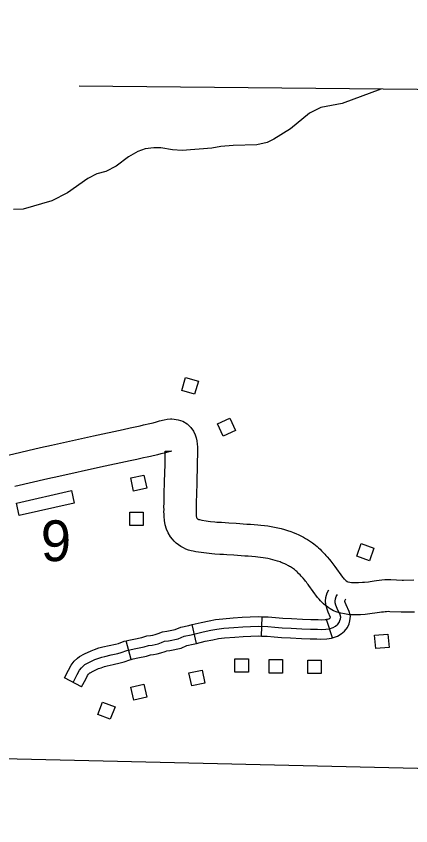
# Model space of a CAD drawing. Extents: x -19 to 366, y -4 to 359.
# Drawn here: x 137.637 to 138.218, y 202.996 to 204.187 of the extents above; entities that cross this region are included whole.
import ezdxf

# ---------------------------------------------------------------- set-up
doc = ezdxf.new("R2010")
doc.units = 0
for name, color, linetype in [('Level 10', 7, 'Continuous'), ('Level 2', 7, 'Continuous'), ('Level 32', 7, 'Continuous'), ('Level 35', 7, 'Continuous'), ('Level 5', 7, 'Continuous'), ('Level 56', 7, 'Continuous'), ('Level 60', 7, 'Continuous')]:
    doc.layers.add(name, color=color, linetype=linetype)

msp = doc.modelspace()

# ---------------------------------------------------------------- linework, layer by layer
at = {"layer": 'Level 10'}
for p, q in [((137.6726, 203.552), (137.6889, 203.5558)), ((137.6247, 203.5411), (137.6726, 203.552)), ((137.865, 203.5468), (137.8653, 203.5468)), ((137.6832, 203.5059), (137.6349, 203.4949)), ((137.6994, 203.5096), (137.6832, 203.5059)), ((137.6832, 203.5059), (137.6832, 203.5059)), ((137.6993, 203.5096), (137.6994, 203.5096)), ((138.1236, 203.355), (138.1228, 203.3556)), ((138.096, 203.3166), (138.0952, 203.3172))]:
    msp.add_line(p, q, dxfattribs=at)
for points in [[(137.6889, 203.5558), (137.7504, 203.5695), (137.7943, 203.5789), (137.8043, 203.5811), (137.8142, 203.5831), (137.819, 203.5842), (137.8239, 203.5853), (137.8333, 203.5875), (137.8382, 203.5887), (137.8431, 203.5899), (137.8478, 203.5912), (137.8543, 203.5929), (137.8589, 203.5938), (137.8638, 203.5942), (137.8659, 203.5942)], [(137.8659, 203.5942), (137.8691, 203.5941), (137.8753, 203.5931), (137.882, 203.5908), (137.8885, 203.5868), (137.8937, 203.5817), (137.8977, 203.5761), (137.9001, 203.5706), (137.9016, 203.5662), (137.9026, 203.5618), (137.9032, 203.5573), (137.9035, 203.5532), (137.9035, 203.5473), (137.9032, 203.5261), (137.9024, 203.5011), (137.902, 203.4823), (137.9019, 203.4789), (137.9018, 203.476), (137.9017, 203.473), (137.9016, 203.47), (137.9016, 203.4642), (137.9016, 203.461), (137.9016, 203.4581), (137.9017, 203.4552), (137.9017, 203.4526), (137.9018, 203.451), (137.902, 203.4502), (137.9023, 203.4492), (137.9027, 203.4482), (137.9032, 203.4475), (137.9035, 203.4471), (137.9035, 203.4471), (137.9037, 203.447), (137.9042, 203.4467), (137.9043, 203.4466), (137.9047, 203.4465), (137.9051, 203.4463), (137.9065, 203.4461), (137.9097, 203.4454), (137.9162, 203.4444), (137.9193, 203.4439), (137.9225, 203.4435), (137.929, 203.4428), (137.932, 203.4425), (137.9391, 203.4421), (137.9444, 203.4418), (137.9496, 203.4415), (137.9605, 203.4408), (137.9658, 203.4404), (137.971, 203.44), (137.9764, 203.4396), (137.9816, 203.4393), (137.9923, 203.4385), (137.997, 203.4381), (138.0021, 203.4375), (138.0069, 203.4369), (138.0119, 203.4361), (138.0168, 203.4351), (138.0217, 203.434), (138.0265, 203.4328), (138.0314, 203.4315), (138.0362, 203.4299), (138.0407, 203.4284), (138.0436, 203.4274), (138.0491, 203.4251), (138.0517, 203.424), (138.0546, 203.4227), (138.0598, 203.42), (138.0626, 203.4185), (138.0654, 203.4167), (138.0701, 203.4137), (138.0726, 203.4119), (138.0748, 203.4103), (138.0772, 203.4085), (138.0795, 203.4065), (138.0818, 203.4045), (138.0839, 203.4025), (138.0861, 203.4003), (138.088, 203.3982), (138.0895, 203.3965), (138.0909, 203.395), (138.0926, 203.3931), (138.0944, 203.3912), (138.0978, 203.3872), (138.0996, 203.385), (138.1013, 203.3829), (138.1028, 203.3809), (138.1043, 203.3789), (138.1058, 203.3769), (138.1171, 203.3612), (138.1178, 203.3604), (138.119, 203.3591), (138.1198, 203.3583), (138.1212, 203.3571), (138.1224, 203.3559), (138.1236, 203.355)], [(137.8653, 203.5468), (137.8651, 203.5468), (137.8649, 203.5468), (137.86, 203.5454), (137.8547, 203.544), (137.8498, 203.5428), (137.8447, 203.5415), (137.8344, 203.5391), (137.8293, 203.538), (137.8241, 203.5368), (137.8141, 203.5347), (137.8043, 203.5326), (137.7606, 203.5232), (137.6993, 203.5096)], [(138.0952, 203.3172), (138.0919, 203.3196), (138.0891, 203.3223), (138.0869, 203.3242), (138.0845, 203.3267), (138.0825, 203.3289), (138.0801, 203.3317), (138.0676, 203.3489), (138.0664, 203.3506), (138.0651, 203.3523), (138.0639, 203.3539), (138.0626, 203.3555), (138.0616, 203.3568), (138.059, 203.3597), (138.0576, 203.3613), (138.0562, 203.3628), (138.0545, 203.3646), (138.0529, 203.3664), (138.0519, 203.3675), (138.0508, 203.3687), (138.0497, 203.3697), (138.0485, 203.3707), (138.0475, 203.3716), (138.0462, 203.3725), (138.0448, 203.3736), (138.0436, 203.3745), (138.0404, 203.3765), (138.0391, 203.3773), (138.0375, 203.3782), (138.034, 203.38), (138.0323, 203.3808), (138.0304, 203.3816), (138.0267, 203.3831), (138.0251, 203.3837), (138.0214, 203.385), (138.0179, 203.3861), (138.0144, 203.387), (138.0108, 203.388), (138.0072, 203.3888), (138.0036, 203.3895), (138, 203.39), (137.9963, 203.3905), (137.9926, 203.391), (137.9887, 203.3912), (137.9782, 203.3921), (137.973, 203.3924), (137.9677, 203.3928), (137.9624, 203.3932), (137.9571, 203.3936), (137.9468, 203.3942), (137.9416, 203.3945), (137.9362, 203.3949), (137.9289, 203.3953), (137.9246, 203.3956), (137.9169, 203.3965), (137.9128, 203.397), (137.9088, 203.3976), (137.9011, 203.3989), (137.8971, 203.3997), (137.8942, 203.4002), (137.8904, 203.4013), (137.8866, 203.4027), (137.8828, 203.4044), (137.8789, 203.4065), (137.8757, 203.4088), (137.8724, 203.4113), (137.8693, 203.4144), (137.8667, 203.4172), (137.864, 203.4207), (137.8606, 203.4264), (137.8581, 203.4322), (137.856, 203.4383), (137.8548, 203.4447), (137.8544, 203.4505), (137.8543, 203.4543), (137.8542, 203.4576), (137.8543, 203.461), (137.8542, 203.4642), (137.8543, 203.4709), (137.8544, 203.4741), (137.8544, 203.4774), (137.8546, 203.4807), (137.8547, 203.4835), (137.8551, 203.5023), (137.8558, 203.5272), (137.8561, 203.547), (137.865, 203.5468)], [(138.1228, 203.3556), (138.1234, 203.3552), (138.124, 203.3549), (138.1246, 203.3546), (138.1254, 203.3544), (138.1276, 203.354), (138.1301, 203.3536), (138.1327, 203.3534), (138.1355, 203.3533), (138.1382, 203.3533), (138.1406, 203.3534), (138.1465, 203.3538), (138.1492, 203.3541), (138.1552, 203.3547), (138.1579, 203.3551), (138.1638, 203.356), (138.167, 203.3565), (138.1709, 203.3571), (138.175, 203.3576), (138.1795, 203.3579), (138.1837, 203.358), (138.1879, 203.358), (138.205, 203.3572), (138.207, 203.3572), (138.2222, 203.3573)], [(138.223, 203.3099), (138.2067, 203.3098), (138.2035, 203.3099), (138.1867, 203.3106), (138.1842, 203.3107), (138.1818, 203.3106), (138.1796, 203.3104), (138.1772, 203.3101), (138.1744, 203.3097), (138.1713, 203.3092), (138.1645, 203.3082), (138.1608, 203.3077), (138.1539, 203.307), (138.1503, 203.3066), (138.1434, 203.3062), (138.1393, 203.306), (138.1345, 203.306), (138.1298, 203.3061), (138.1248, 203.3066), (138.1198, 203.3073), (138.1147, 203.3083), (138.1092, 203.3097), (138.1038, 203.312), (138.0988, 203.3146), (138.096, 203.3166)]]:
    msp.add_lwpolyline(points, dxfattribs=at)
at = {"layer": 'Level 2'}
msp.add_lwpolyline([(139.3896, 204.0685), (138.383, 204.0778), (138.3761, 204.0776), (137.7294, 204.084)], dxfattribs=at)
at = {"layer": 'Level 32'}
for p, q in [((137.9976, 203.2748), (137.9985, 203.3032)), ((137.9022, 203.264), (137.8957, 203.2916)), ((138.1024, 203.2721), (138.0932, 203.2989)), ((137.8058, 203.2403), (137.7986, 203.2678)), ((137.733, 203.1998), (137.7079, 203.2132))]:
    msp.add_line(p, q, dxfattribs=at)
for points in [[(138.0932, 203.2989), (138.0971, 203.3003), (138.0984, 203.3011), (138.0995, 203.302), (138.0959, 203.3098), (138.0937, 203.3159), (138.0923, 203.3217), (138.0921, 203.3263), (138.0924, 203.3317), (138.0944, 203.3383), (138.0969, 203.3429)], [(137.7204, 203.2065), (137.7266, 203.218), (137.7297, 203.2244), (137.7326, 203.2282), (137.7361, 203.2315), (137.7377, 203.2328), (137.7434, 203.2357), (137.7523, 203.24), (137.7568, 203.2415), (137.7626, 203.2438), (137.7672, 203.2448), (137.7765, 203.2469), (137.7862, 203.2491), (137.7913, 203.2504), (137.7997, 203.2534), (137.8058, 203.255), (137.8128, 203.2565), (137.825, 203.259), (137.8315, 203.261), (137.8366, 203.2615), (137.8411, 203.2624), (137.8455, 203.2635), (137.8508, 203.2654), (137.8552, 203.2672), (137.8607, 203.2677), (137.8751, 203.2706), (137.8837, 203.2744), (137.8941, 203.2767), (137.912, 203.2809), (137.9234, 203.2832), (137.9322, 203.2849), (137.9421, 203.2861), (137.9571, 203.2873), (137.9701, 203.2884), (137.9818, 203.2889), (137.9928, 203.2891), (138.0071, 203.2887), (138.0173, 203.2879), (138.028, 203.287), (138.0413, 203.2863), (138.0573, 203.2855), (138.0698, 203.285), (138.0802, 203.2848), (138.0854, 203.2844), (138.0926, 203.2848), (138.0977, 203.2854), (138.1033, 203.2874), (138.1067, 203.2895), (138.1099, 203.2921), (138.1121, 203.2949), (138.1132, 203.2974), (138.114, 203.3), (138.1143, 203.3027), (138.1134, 203.3058), (138.1091, 203.3153), (138.1073, 203.32), (138.1064, 203.3237), (138.1063, 203.3261), (138.1065, 203.3293), (138.1076, 203.3328), (138.1094, 203.3361)], [(138.1024, 203.2721), (138.1095, 203.2745), (138.1151, 203.278), (138.12, 203.2821), (138.1242, 203.2873), (138.1266, 203.2925), (138.1279, 203.2971), (138.1288, 203.3038), (138.1268, 203.3108), (138.1222, 203.3207), (138.1209, 203.3242), (138.1206, 203.3256), (138.1206, 203.326), (138.1206, 203.3268), (138.1208, 203.3273), (138.1219, 203.3293)], [(137.8957, 203.2916), (137.9089, 203.2947), (137.9206, 203.2971), (137.93, 203.299), (137.9407, 203.3002), (137.956, 203.3014), (137.9691, 203.3026), (137.9813, 203.3031), (137.9928, 203.3034), (137.9985, 203.3032)], [(137.9985, 203.3032), (138.0078, 203.3029), (138.0185, 203.3021), (138.029, 203.3012), (138.0421, 203.3005), (138.0579, 203.2997), (138.0702, 203.2992), (138.081, 203.299), (138.0857, 203.2986), (138.0913, 203.2989), (138.0944, 203.2993), (138.0932, 203.2989)], [(137.7986, 203.2678), (137.8025, 203.2688), (137.8099, 203.2704), (137.8215, 203.2728), (137.8288, 203.2749), (137.8344, 203.2755), (137.8379, 203.2762), (137.8413, 203.2771), (137.8457, 203.2787), (137.8519, 203.2811), (137.8586, 203.2818), (137.8708, 203.2843), (137.8792, 203.288), (137.8909, 203.2905), (137.8957, 203.2916)], [(137.7079, 203.2132), (137.7139, 203.2244), (137.7175, 203.2319), (137.722, 203.2378), (137.7268, 203.2422), (137.73, 203.2448), (137.7371, 203.2484), (137.7469, 203.2531), (137.7519, 203.2549), (137.7584, 203.2574), (137.7641, 203.2587), (137.7734, 203.2608), (137.7829, 203.2629), (137.7871, 203.264), (137.7955, 203.267), (137.7986, 203.2678)], [(137.9022, 203.264), (137.915, 203.267), (137.9262, 203.2692), (137.9344, 203.2709), (137.9435, 203.272), (137.9583, 203.2731), (137.971, 203.2742), (137.9823, 203.2747), (137.9927, 203.2749), (137.9976, 203.2748)], [(137.9976, 203.2748), (138.0063, 203.2745), (138.0162, 203.2738), (138.0271, 203.2728), (138.0406, 203.2721), (138.0566, 203.2713), (138.0694, 203.2708), (138.0794, 203.2706), (138.0852, 203.2701), (138.094, 203.2706), (138.101, 203.2716), (138.1025, 203.2721)], [(137.8058, 203.2403), (137.809, 203.2412), (137.8157, 203.2426), (137.8285, 203.2452), (137.8343, 203.247), (137.8388, 203.2474), (137.8443, 203.2485), (137.8497, 203.2499), (137.8558, 203.2522), (137.8586, 203.2532), (137.8628, 203.2536), (137.8795, 203.257), (137.8881, 203.2608), (137.8972, 203.2628), (137.9022, 203.264)], [(137.733, 203.1998), (137.7393, 203.2115), (137.7419, 203.2169), (137.7432, 203.2186), (137.7453, 203.2207), (137.7455, 203.2208), (137.7498, 203.223), (137.7577, 203.2268), (137.7617, 203.2282), (137.7668, 203.2301), (137.7704, 203.231), (137.7795, 203.233), (137.7895, 203.2353), (137.7955, 203.2368), (137.8039, 203.2398), (137.8058, 203.2403)]]:
    msp.add_lwpolyline(points, dxfattribs=at)
at = {"layer": 'Level 35'}
msp.add_lwpolyline([(138.1735, 204.0796), (138.1166, 204.0584), (138.0852, 204.0523), (138.0686, 204.0439), (138.0406, 204.0212), (138.0161, 204.006), (138.0059, 204.0011), (137.9907, 203.9976), (137.956, 203.9965), (137.9378, 203.995), (137.9246, 203.9927), (137.8811, 203.9893), (137.8668, 203.99), (137.8494, 203.993), (137.8392, 203.993), (137.8263, 203.9915), (137.8157, 203.9877), (137.8018, 203.9801), (137.784, 203.9661), (137.7685, 203.9581), (137.7553, 203.9547), (137.7421, 203.9479), (137.7122, 203.927), (137.6892, 203.9152), (137.6468, 203.9027), (137.6325, 203.9023)], dxfattribs=at)
at = {"layer": 'Level 5'}
msp.add_lwpolyline([(137.3855, 203.0998), (138.3744, 203.0767)], dxfattribs=at)
at = {"layer": 'Level 56'}
for points in [[(137.8993, 203.6308), (137.8804, 203.6362), (137.8858, 203.6552), (137.9048, 203.6498)], [(137.9413, 203.5689), (137.9331, 203.5868), (137.951, 203.5951), (137.9593, 203.5772)], [(137.8095, 203.4881), (137.8052, 203.5073), (137.8246, 203.5116), (137.8288, 203.4923)], [(137.6413, 203.452), (137.6371, 203.4704), (137.7179, 203.4887), (137.7221, 203.4702)], [(137.8041, 203.4375), (137.804, 203.4572), (137.8238, 203.4572), (137.8238, 203.4375)], [(138.1632, 203.4041), (138.1565, 203.3856), (138.1379, 203.3922), (138.1445, 203.4108)], [(138.1658, 203.2562), (138.1641, 203.2758), (138.1837, 203.2776), (138.1855, 203.2579)], [(137.9587, 203.2214), (137.9586, 203.2411), (137.9784, 203.2411), (137.9784, 203.2214)], [(138.0091, 203.2203), (138.0091, 203.24), (138.0289, 203.24), (138.0289, 203.2203)], [(138.066, 203.2198), (138.0659, 203.2395), (138.0857, 203.2395), (138.0857, 203.2198)], [(137.8951, 203.2013), (137.891, 203.2205), (137.9103, 203.2247), (137.9145, 203.2054)], [(137.829, 203.1848), (137.8097, 203.1804), (137.8054, 203.1997), (137.8246, 203.2041)], [(137.7568, 203.1593), (137.7639, 203.1777), (137.7823, 203.1706), (137.7752, 203.1522)]]:
    msp.add_lwpolyline(points, close=True, dxfattribs=at)
at = {"layer": 'Level 60'}
for points in [[(139.4406, 1.5315), (139.2511, 10.1473), (139.0608, 18.7633), (138.8699, 27.3793), (138.6784, 35.9956), (138.4861, 44.6119), (138.2932, 53.2285), (138.0997, 61.8451), (137.9055, 70.4619), (137.7106, 79.0789), (137.5151, 87.6959), (137.319, 96.3132), (137.1221, 104.9306), (136.9247, 113.5481), (136.7265, 122.1658), (136.5278, 130.7836), (136.3283, 139.4016), (136.1282, 148.0197), (135.9275, 156.6379), (135.7261, 165.2564), (135.5241, 173.8749), (135.3214, 182.4936), (135.1181, 191.1125), (134.9141, 199.7315), (134.7095, 208.3506), (134.5043, 216.9699), (134.2984, 225.5894), (134.0919, 234.209), (133.8847, 242.8288), (133.6769, 251.4487), (133.4685, 260.0687), (133.2594, 268.6889), (133.0497, 277.3093), (132.8393, 285.9298), (132.6283, 294.5504), (132.4167, 303.1713), (132.2044, 311.7922), (131.9916, 320.4133), (131.778, 329.0346), (131.5639, 337.656), (131.3491, 346.2776)], [(0, 198.1326), (7.1014, 198.137), (14.2028, 198.1503), (21.3042, 198.1724), (28.4055, 198.2034), (35.5068, 198.2433), (42.6081, 198.292), (49.7092, 198.3496), (56.8103, 198.4161), (63.9113, 198.4913), (71.0123, 198.5755), (78.1131, 198.6685), (85.2137, 198.7704), (92.3143, 198.8811), (99.4147, 199.0007), (106.5149, 199.1291), (113.615, 199.2664), (120.7149, 199.4126), (127.8146, 199.5676), (134.9141, 199.7315), (142.0135, 199.9042), (149.1125, 200.0858), (156.2114, 200.2762), (163.31, 200.4755), (170.4084, 200.6837), (177.5065, 200.9007), (184.6043, 201.1265), (191.7018, 201.3612), (198.799, 201.6048), (205.896, 201.8572), (212.9926, 202.1185), (220.0888, 202.3886), (227.1848, 202.6676), (234.2803, 202.9554), (241.3755, 203.2521), (248.4704, 203.5576), (255.5648, 203.872), (262.6589, 204.1952), (269.7525, 204.5273), (276.8457, 204.8682), (283.9385, 205.218), (291.0309, 205.5766), (298.1228, 205.9441), (305.2142, 206.3204), (312.3051, 206.7056), (319.3956, 207.0996), (326.4856, 207.5024), (333.5751, 207.9141), (340.664, 208.3347)]]:
    msp.add_spline(points, degree=3, dxfattribs=at)

# ---------------------------------------------------------------- texts
at = {"layer": 'Level 56'}
msp.add_text('9', height=0.06, dxfattribs=at).set_placement((137.6729, 203.385))

doc.saveas('drawing.dxf')
